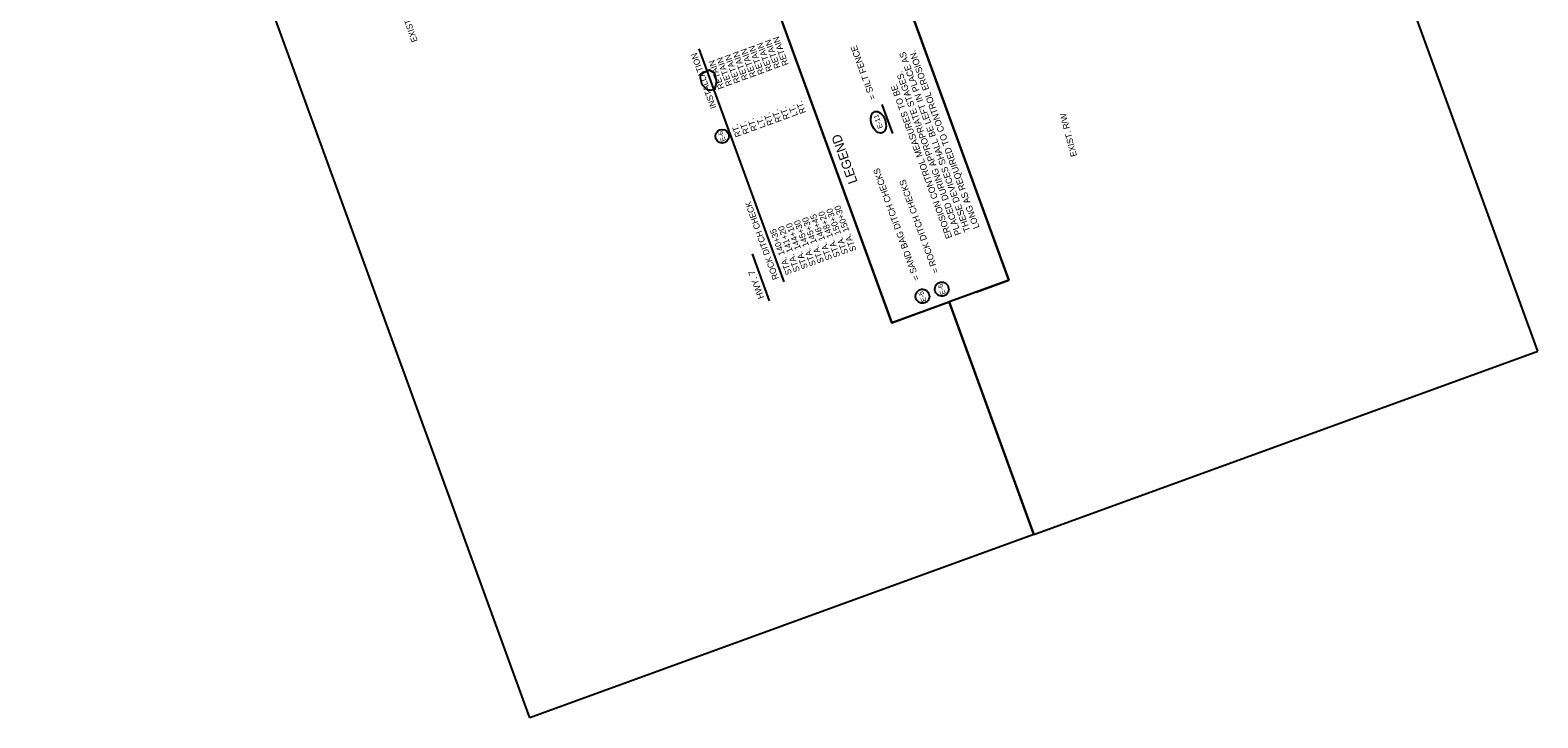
# Model space of a CAD drawing. Extents: x 986289 to 987754, y 1871116 to 1872971.
# Drawn here: x 986289 to 987754, y 1871116 to 1871784 of the extents above; entities that cross this region are included whole.
import ezdxf

# ---------------------------------------------------------------- set-up
doc = ezdxf.new("R2010")
doc.units = 0
for name, color, linetype in [('1', 7, 'Continuous'), ('44', 7, 'Continuous'), ('Level 1', 7, 'Continuous'), ('Level 44', 7, 'Continuous'), ('NO PLOT', 7, 'Continuous'), ('R_Draft', 7, 'Continuous'), ('S_TREE', 7, 'Continuous')]:
    doc.layers.add(name, color=color, linetype=linetype)

msp = doc.modelspace()

# ---------------------------------------------------------------- linework, layer by layer
at = {"layer": '1'}
for p, q in [((987125.9, 1871499.6), (987008.8, 1871821.6)), ((987207.8, 1871529.4), (987125.9, 1871499.6)), ((987263.9, 1871293.8), (987181.7, 1871519.9))]:
    msp.add_line(p, q, dxfattribs=at)
msp.add_lwpolyline([(987207.8, 1871529.4), (987239.7, 1871541), (987122.5, 1871863)], dxfattribs=at)
msp.add_circle((986961.1, 1871680.9), 6.61, dxfattribs=at)
at = {"layer": '44'}
for p, q in [((987021.3, 1871539.5), (986938.9, 1871765.9)), ((987007.2, 1871520.8), (986990.5, 1871566.7))]:
    msp.add_line(p, q, dxfattribs=at)
at = {"layer": 'Level 1'}
for centre, major_axis, ratio in [((987112.9, 1871694.5), (-3.7, 10.3), 0.622952), ((987174.5, 1871532.3), (2.35, -6.47), 0.97521), ((987155.7, 1871525.4), (2.35, -6.47), 0.97521)]:
    msp.add_ellipse(centre, major_axis=major_axis, ratio=ratio, dxfattribs=at)
at = {"layer": 'Level 44'}
msp.add_lwpolyline([(987126.8, 1871683.5), (987116.5, 1871711.8)], dxfattribs=at)
at = {"layer": 'NO PLOT'}
for points in [[(987753.7, 1871472.1), (987208, 1872971.2), (986718.3, 1872793), (986821.2, 1872510.2), (986884.7, 1872533.2), (987030, 1872133.9), (986966.6, 1872110.8), (987064.5, 1871841.9), (987122.5, 1871863), (987239.7, 1871541), (987181.7, 1871519.9), (987263.9, 1871293.8)], [(987753.7, 1871472.1), (987208, 1872971.2), (986718.3, 1872793), (986821.2, 1872510.2), (986884.7, 1872533.2), (987030, 1872133.9), (986966.6, 1872110.8), (987064.5, 1871841.9), (987122.5, 1871863), (987239.7, 1871541), (987181.7, 1871519.9), (987263.9, 1871293.8)], [(987753.7, 1871472.1), (987208, 1872971.2), (986718.3, 1872793), (986821.2, 1872510.2), (986884.7, 1872533.2), (987030, 1872133.9), (986966.6, 1872110.8), (987064.5, 1871841.9), (987122.5, 1871863), (987239.7, 1871541), (987181.7, 1871519.9), (987263.9, 1871293.8)], [(987753.7, 1871472.1), (987208, 1872971.2), (986718.3, 1872793), (986821.2, 1872510.2), (986884.7, 1872533.2), (987030, 1872133.9), (986966.6, 1872110.8), (987064.5, 1871841.9), (987122.5, 1871863), (987239.7, 1871541), (987181.7, 1871519.9), (987263.9, 1871293.8)], [(987753.7, 1871472.1), (987208, 1872971.2), (986718.3, 1872793), (986821.2, 1872510.2), (986884.7, 1872533.2), (987030, 1872133.9), (986966.6, 1872110.8), (987064.5, 1871841.9), (987122.5, 1871863), (987239.7, 1871541), (987181.7, 1871519.9), (987263.9, 1871293.8)], [(987753.7, 1871472.1), (987208, 1872971.2), (986718.3, 1872793), (986821.2, 1872510.2), (986884.7, 1872533.2), (987030, 1872133.9), (986966.6, 1872110.8), (987064.5, 1871841.9), (987122.5, 1871863), (987239.7, 1871541), (987181.7, 1871519.9), (987263.9, 1871293.8)], [(987753.7, 1871472.1), (987208, 1872971.2), (986718.3, 1872793), (986821.2, 1872510.2), (986884.7, 1872533.2), (987030, 1872133.9), (986966.6, 1872110.8), (987064.5, 1871841.9), (987122.5, 1871863), (987239.7, 1871541), (987181.7, 1871519.9), (987263.9, 1871293.8)], [(986774.2, 1871115.6), (986369.2, 1872228.3), (986415.6, 1872245.1), (986348.7, 1872429.1), (986362.4, 1872434.1), (986288.7, 1872636.6), (986718.3, 1872793), (986821.2, 1872510.2), (986748.9, 1872483.8), (986894.2, 1872084.4), (986966.6, 1872110.8), (987064.5, 1871841.9), (987008.8, 1871821.6), (987125.9, 1871499.6), (987181.7, 1871519.9), (987263.9, 1871293.8)], [(986774.2, 1871115.6), (986369.2, 1872228.3), (986415.6, 1872245.1), (986348.7, 1872429.1), (986362.4, 1872434.1), (986288.7, 1872636.6), (986718.3, 1872793), (986821.2, 1872510.2), (986748.9, 1872483.8), (986894.2, 1872084.4), (986966.6, 1872110.8), (987064.5, 1871841.9), (987008.8, 1871821.6), (987125.9, 1871499.6), (987181.7, 1871519.9), (987263.9, 1871293.8)], [(986774.2, 1871115.6), (986369.2, 1872228.3), (986415.6, 1872245.1), (986348.7, 1872429.1), (986362.4, 1872434.1), (986288.7, 1872636.6), (986718.3, 1872793), (986821.2, 1872510.2), (986748.9, 1872483.8), (986894.2, 1872084.4), (986966.6, 1872110.8), (987064.5, 1871841.9), (987008.8, 1871821.6), (987125.9, 1871499.6), (987181.7, 1871519.9), (987263.9, 1871293.8)], [(986774.2, 1871115.6), (986369.2, 1872228.3), (986415.6, 1872245.1), (986348.7, 1872429.1), (986362.4, 1872434.1), (986288.7, 1872636.6), (986718.3, 1872793), (986821.2, 1872510.2), (986748.9, 1872483.8), (986894.2, 1872084.4), (986966.6, 1872110.8), (987064.5, 1871841.9), (987008.8, 1871821.6), (987125.9, 1871499.6), (987181.7, 1871519.9), (987263.9, 1871293.8)], [(986774.2, 1871115.6), (986369.2, 1872228.3), (986415.6, 1872245.1), (986348.7, 1872429.1), (986362.4, 1872434.1), (986288.7, 1872636.6), (986718.3, 1872793), (986821.2, 1872510.2), (986748.9, 1872483.8), (986894.2, 1872084.4), (986966.6, 1872110.8), (987064.5, 1871841.9), (987008.8, 1871821.6), (987125.9, 1871499.6), (987181.7, 1871519.9), (987263.9, 1871293.8)], [(986774.2, 1871115.6), (986369.2, 1872228.3), (986415.6, 1872245.1), (986348.7, 1872429.1), (986362.4, 1872434.1), (986288.7, 1872636.6), (986718.3, 1872793), (986821.2, 1872510.2), (986748.9, 1872483.8), (986894.2, 1872084.4), (986966.6, 1872110.8), (987064.5, 1871841.9), (987008.8, 1871821.6), (987125.9, 1871499.6), (987181.7, 1871519.9), (987263.9, 1871293.8)]]:
    msp.add_lwpolyline(points, close=True, dxfattribs=at)
at = {"layer": 'S_TREE'}
msp.add_lwpolyline([(986941, 1871741.8), (986948.5, 1871745.3), (986953.3, 1871742.6), (986955.5, 1871733.7), (986953.5, 1871726.3), (986947.8, 1871725.1), (986941.8, 1871731), (986939.9, 1871737.4), (986940.5, 1871741.1), (986941.7, 1871742.3)], dxfattribs=at)

# ---------------------------------------------------------------- texts
at = {"layer": '1'}
msp.add_text('E-6 ', height=4.8, rotation=110, dxfattribs=at).set_placement((986964.8, 1871676.7))
at = {"layer": '44'}
for s, height, p in [('RETAIN', 6, (987010.2, 1871745)), ('RETAIN', 6, (987018, 1871747.9)), ('RETAIN', 6, (987025.8, 1871750.7)), ('INSTALLATION', 6, (986955.7, 1871708.9)), ('RETAIN', 6, (986971.1, 1871730.8)), ('RETAIN', 6, (986978.9, 1871733.6)), ('RETAIN', 6, (986986.7, 1871736.5)), ('RETAIN', 6, (986994.5, 1871739.3)), ('RETAIN', 6, (987002.3, 1871742.1)), ('RETAIN', 6, (986963.3, 1871727.9)), ('RT.', 6, (987042.7, 1871704)), ('RT.', 6, (986995.7, 1871687)), ('LT.', 6, (987003.5, 1871689.9)), ('RT.', 6, (987011.3, 1871692.6)), ('RT.', 6, (987019.2, 1871695.5)), ('RT.', 6, (987027, 1871698.3)), ('LT.', 6, (987034.8, 1871701.3)), ('RT.', 6, (986980.1, 1871681.3)), ('RT.', 6, (986987.9, 1871684.1)), ('ROCK DITCH CHECK', 6, (987016.2, 1871542.7)), ('STA. 150+30', 6, (987083.7, 1871567.3)), ('STA. 150+30', 6, (987091.6, 1871570.1)), ('STA. 144+10', 6, (987044.6, 1871553)), ('STA. 145+30', 6, (987052.4, 1871555.9)), ('STA. 145+30', 6, (987060.2, 1871558.7)), ('STA. 146+45', 6, (987068.1, 1871561.6)), ('STA. 148+20', 6, (987075.9, 1871564.4)), ('STA. 140+35', 6, (987029, 1871547.4)), ('STA. 141+20', 6, (987036.8, 1871550.2)), ('HWY. 7', 6.25, (987002, 1871524.1))]:
    msp.add_text(s, height=height, rotation=110, dxfattribs=at).set_placement(p)
at = {"layer": 'Level 1'}
for s, height, p in [('= SILT FENCE', 6.25, (987110.6, 1871717.6)), ('THESE DEVICES SHALL BE LEFT IN PLACE AS ', 6.25, (987202.4, 1871589.1)), ('LONG AS REQUIRED TO CONTROL EROSION.', 6.25, (987211.3, 1871592.3)), ('PLACED DURING APPROPRIATE STAGES. ', 6.25, (987193.6, 1871585.9)), ('EROSION CONTROL MEASURES TO BE', 6.25, (987184.8, 1871582.7)), ('E-11 ', 4.88, (987117.3, 1871689.3)), ('= SAND BAG DITCH CHECKS', 6.25, (987153, 1871542)), ('= ROCK DITCH CHECKS', 6.25, (987171.8, 1871548.9)), ('E-5 ', 4.88, (987159.7, 1871520.9)), ('E-6 ', 4.88, (987178.4, 1871527.9))]:
    msp.add_text(s, height=height, rotation=110, dxfattribs=at).set_placement(p)
at = {"layer": 'Level 44'}
msp.add_text('LEGEND', height=9.14, rotation=110, dxfattribs=at).set_placement((987092.8, 1871636.6))
at = {"layer": 'R_Draft'}
for rotation, p in [(109.2927, (986665.3, 1871773.5)), (104.7013, (987305.9, 1871661.9))]:
    msp.add_text('EXIST. R/W', height=6, rotation=rotation, dxfattribs=at).set_placement(p)

doc.saveas('drawing.dxf')
